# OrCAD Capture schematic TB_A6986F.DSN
size C
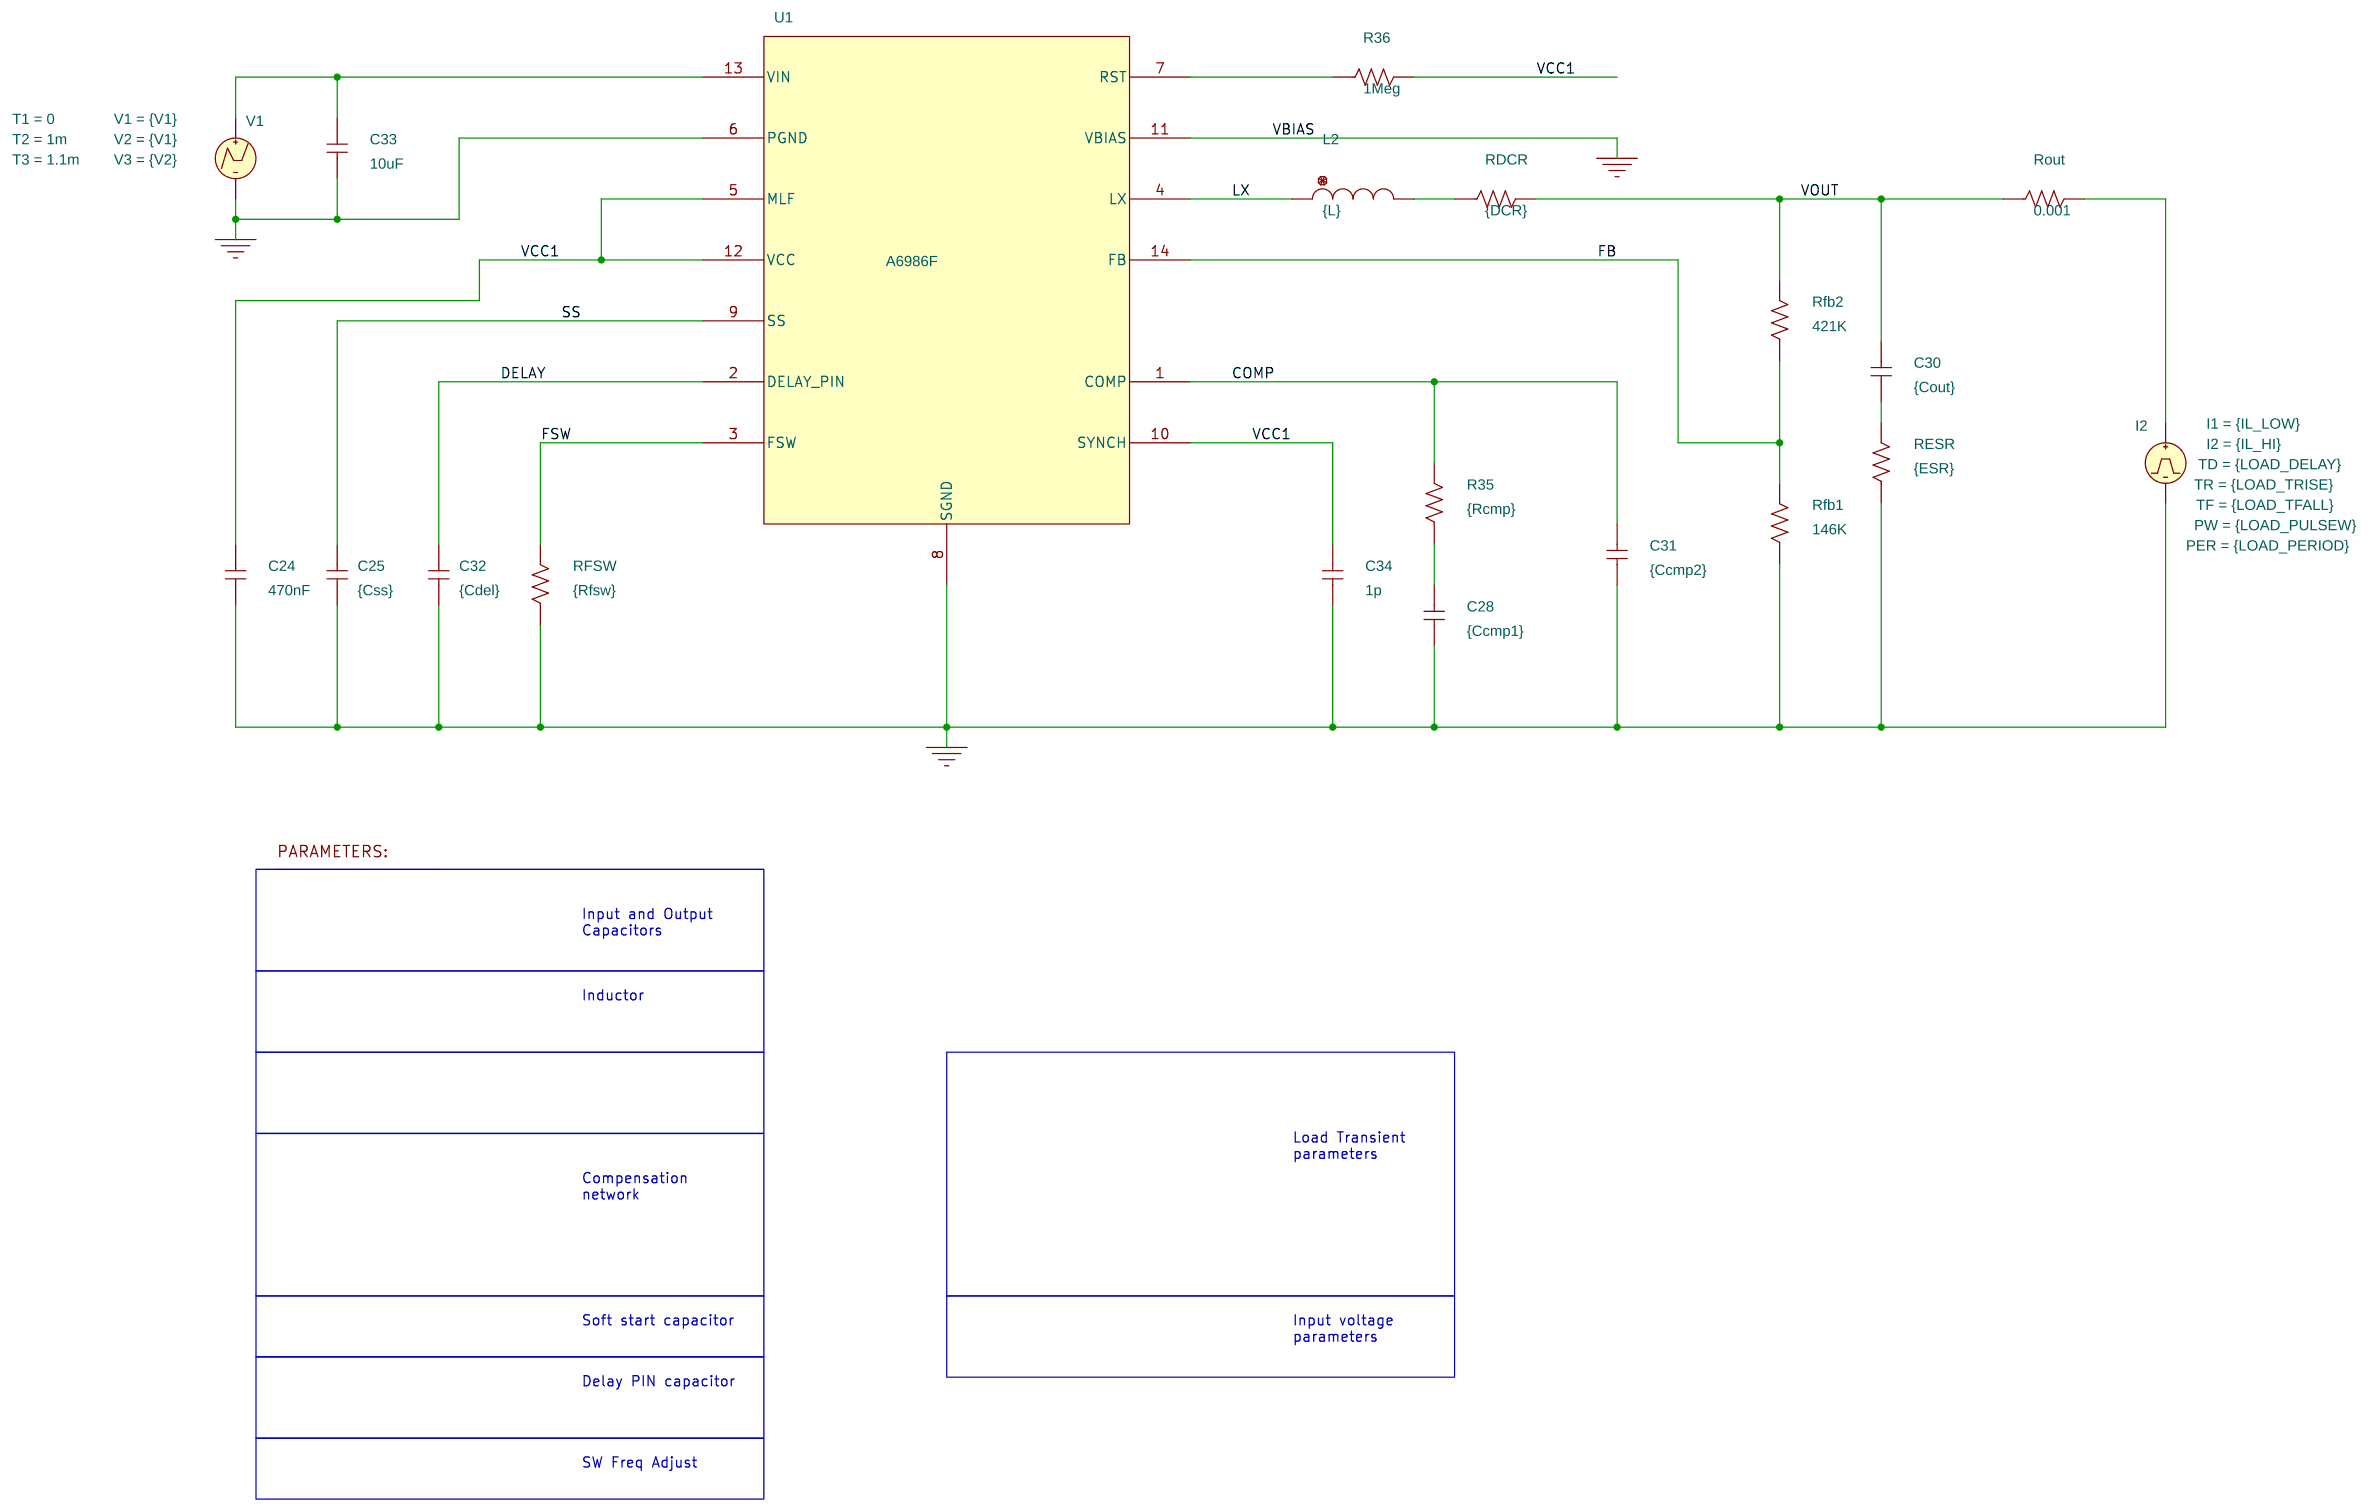
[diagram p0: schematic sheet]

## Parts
2  PARAM
C24  470nF  [RAD/CK05]
C25  {Css}  [RAD/CK05]
C28  {Ccmp1}  [RAD/CK05]
C30  {Cout}  [RAD/CK05]
C31  {Ccmp2}  [RAD/CK05]
C32  {Cdel}  [RAD/CK05]
C33  10uF  [RAD/CK05]
C34  1p  [RAD/CK05]
I2  IPULSE
L2  {L}  [DISC/.350x.175/LS.200x.100/.034]
R35  {Rcmp}  [AX/RC05]
R36  1Meg  [AX/RC05]
RDCR  {DCR}  [AX/RC05]
RESR  {ESR}  [AX/RC05]
Rfb1  146K  [AX/RC05]
Rfb2  421K  [AX/RC05]
RFSW  {Rfsw}  [AX/RC05]
Rout  0.001  [AX/RC05]
U1  A6986F
V1  VPWL

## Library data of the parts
2 = PARAM: Ccmp1: 330pF; Ccmp2: 2pF; Cdel: 0.1nF; Cin: 10u; Cout: 10u; Css: 1nF; DCR: 30m; ESR: 0.001; ILOAD: 1e-9; IL_HI: 1.5; IL_LOW: 100n; L: 4.7u; LOAD_DELAY: 2.5m; LOAD_PERIOD: 10ms; LOAD_PULSEW: 0.5ms; LOAD_TFALL: 1u; LOAD_TRISE: 10u; Rcmp: 80K; Rfsw: 56K; T1: 0; T2: 100us; T3: 10s; V1: 0; V2: 12V
C24 C25 C28 C30 C31 C34 = C: IC: 0
C32 C33 = C
I2 = IPULSE: I1: {IL_LOW}; I2: {IL_HI}; PER: {LOAD_PERIOD}; PW: {LOAD_PULSEW}; TD: {LOAD_DELAY}; TF: {LOAD_TFALL}; TR: {LOAD_TRISE}
L2 = L
R35 R36 RDCR RESR Rfb1 Rfb2 RFSW Rout = R
U1 = A6986F
V1 = VPWL: T1: 0; T2: 1m; T3: 1.1m; V1: {V1}; V2: {V1}; V3: {V2}

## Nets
VCC1: C24.2 C34.2 R36.2 U1.5(MLF) U1.10(SYNCH) U1.12(VCC)
0: C24.1 C25.1 C28.1 C31.1 C32.1 C33.1 C34.1 I2.2(-) RESR.1 Rfb1.1 RFSW.1 U1.6(PGND) U1.8(SGND) U1.11(VBIAS) V1.2(-)
COMP: C31.2 R35.2 U1.1(COMP)
DELAY: C32.2 U1.2(DELAY_PIN)
FB: Rfb1.2 Rfb2.1 U1.14(FB)
FSW: RFSW.2 U1.3(FSW)
LX: L2.1 U1.4(LX)
SS: C25.2 U1.9(SS)
VOUT: C30.1 RDCR.2 Rfb2.2 Rout.1
N3774088: C33.2 U1.13(VIN) V1.1(+)
N3774216: L2.2 RDCR.1
N3774234: C30.2 RESR.2
N3774240: R36.1 U1.7(RST)
N3774406: I2.1(+) Rout.2
N3774494: C28.2 R35.1

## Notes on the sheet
- Input and Output
  Capacitors
- Inductor
- Load Transient
  parameters
- Compensation
  network
- Soft start capacitor
- Input voltage
  parameters
- Delay PIN capacitor
- SW Freq Adjust
